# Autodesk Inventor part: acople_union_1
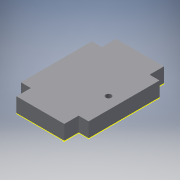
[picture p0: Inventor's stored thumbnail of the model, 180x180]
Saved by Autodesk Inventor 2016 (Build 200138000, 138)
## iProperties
Created: 2017-06
Part Number: acople_union_1
Material: Generic
Document SubType Name: Modeling
Designer: laboratorioesan
Density: 1 g/cm^3
Appearance: Default
Author: laboratorioesan
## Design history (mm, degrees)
sketch "Sketch1"
  geometry: L1 (0, 0)-(-60, 0) reference; L2 (0, 0)-(0, 18.5) reference; L3 (-60, 18.5)-(0, 18.5) reference; L4 (-60, 0)-(-60, 18.5) reference; L5 (-60, 18.5)-(0, 18.5); L6 (0, 18.5)-(0, 0.5); L7 (0, 0.5)-(-60, 0.5); L8 (-60, 0.5)-(-60, 18.5); L9 (-72.5, 18.5)-(12.5, 18.5) reference; L10 (-72.5, 18.5)-(12.5, 18.5); L11 (12.5, 18.5)-(12.5, 107.5); L12 (12.5, 107.5)-(-72.5, 107.5); L13 (-72.5, 107.5)-(-72.5, 18.5); L14 (-60, 107.5)-(0, 107.5); L15 (0, 107.5)-(0, 125.5); L16 (0, 125.5)-(-60, 125.5); L17 (-60, 125.5)-(-60, 107.5)
  constraints: 24 end point, 6 parallel, 3 horizontal, 3 perpendicular, 2 point on line
  dimensions: "d0" = 18 distance of L5.end L6.end; "d1" = 89 distance of L11.end L10.end; "d2" = 18 distance of L15.end L14.end
extrude "Extrusion1" new body sketch "Sketch1" distance "d3" = 18.5; taper "d4" = 0 deg
sketch "Sketch2"
  geometry: L1 (60, 125.5)-(60, 107.5) reference; L2 (0, 125.5)-(60, 125.5) reference; L3 (0, 107.5)-(0, 125.5) reference; L4 (-12.5, 107.5)-(0, 107.5) reference; L5 (-12.5, 18.5)-(-12.5, 107.5) reference; L6 (0, 18.5)-(-12.5, 18.5) reference; L7 (0, 0.5)-(0, 18.5) reference; L8 (60, 0.5)-(0, 0.5) reference; L9 (60, 18.5)-(60, 0.5) reference; L10 (72.5, 18.5)-(60, 18.5) reference; L11 (72.5, 107.5)-(72.5, 18.5) reference; L12 (60, 107.5)-(72.5, 107.5) reference; L13 (101.528, 33.5)-(-101.016, 33.5) reference; C1 r 3.5 at (2.5, 58.5); 1 further point
  constraints: 1 centre point
  dimensions: "d5" = 7 diameter of C1; "d6" = 15 distance from line of L5 C1.centre; "d7" = 25 distance from line of L13 C1.centre
extrude "Extrusion2" cut sketch "Sketch2" distance "d8" = 18.5; taper "d9" = 0 deg
sketch "Sketch3"
  geometry: L1 (60, 125.5)-(60, 107.5) reference; L2 (0, 125.5)-(60, 125.5) reference; L3 (0, 107.5)-(0, 125.5) reference; L4 (-12.5, 107.5)-(0, 107.5) reference; L5 (-12.5, 18.5)-(-12.5, 107.5) reference; L6 (0, 18.5)-(-12.5, 18.5) reference; L7 (0, 0.5)-(0, 18.5) reference; L8 (60, 0.5)-(0, 0.5) reference; L9 (60, 18.5)-(60, 0.5) reference; L10 (72.5, 18.5)-(60, 18.5) reference; L11 (72.5, 107.5)-(72.5, 18.5) reference; L12 (60, 107.5)-(72.5, 107.5) reference; C1 r 3.5 at (2.5, 58.5) reference; 1 further point
  node "Projected Loop2"
body "Solid1"
node "Reference1"
node "Reference2"
node "Projected Loop1"
node "Reference3"
